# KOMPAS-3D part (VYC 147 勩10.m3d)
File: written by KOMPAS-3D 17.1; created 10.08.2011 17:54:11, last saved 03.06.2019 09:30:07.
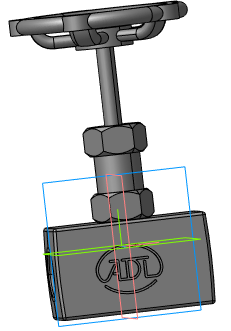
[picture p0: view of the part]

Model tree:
1. Плоскость XY
2. Плоскость ZX
3. Плоскость ZY
4. Ось X
5. Ось Y
6. Ось Z
7. Начало координат
8. Операция без истории:2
